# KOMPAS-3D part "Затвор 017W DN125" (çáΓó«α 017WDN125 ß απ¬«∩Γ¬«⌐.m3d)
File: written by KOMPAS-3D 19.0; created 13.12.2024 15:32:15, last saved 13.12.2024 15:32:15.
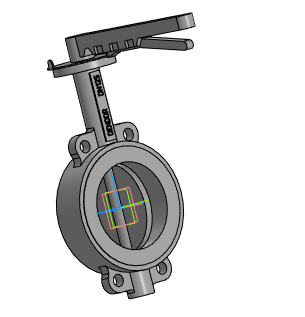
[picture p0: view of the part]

Document properties: Автор: Евгений; Полное имя файла: ..\Затвор 017WDN125.a3d

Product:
- Part/product: Затвор 017W DN125
    Масса: 18.2141

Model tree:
1. Операция без истории:1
